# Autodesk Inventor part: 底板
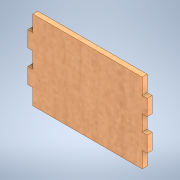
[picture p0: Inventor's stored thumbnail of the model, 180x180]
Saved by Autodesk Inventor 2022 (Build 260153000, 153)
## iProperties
Created: 2024-11
Part Number: 底板
Material: MDF 中密度繊維ボード
Document SubType Name: Modeling
Designer: shimizu
Density: 0.8 g/cm^3
Appearance: サクラ材 - ナチュラル 抑えた光沢
Author: shimizu
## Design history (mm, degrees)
sketch "スケッチ1"
  geometry: L1 (-25.119, 10.226)-(29.881, 10.226); L2 (29.881, -29.774)-(-25.119, -29.774); L3 (-25.119, 2.226)-(-27.619, 2.226); L4 (-27.619, 2.226)-(-27.619, -5.774); L5 (-27.619, -5.774)-(-25.119, -5.774); L6 (-25.119, -13.774)-(-27.619, -13.774); L7 (-27.619, -13.774)-(-27.619, -21.774); L8 (-27.619, -21.774)-(-25.119, -21.774); L9 (29.881, 2.226)-(32.381, 2.226); L10 (32.381, 2.226)-(32.381, -5.774); L11 (32.381, -5.774)-(29.881, -5.774); L12 (29.881, -13.774)-(32.381, -13.774); L13 (32.381, -13.774)-(32.381, -21.774); L14 (32.381, -21.774)-(29.881, -21.774); L15 (-25.119, 2.226)-(-25.119, 10.226); L16 (-25.119, -29.774)-(-25.119, -21.774); L17 (-25.119, -13.774)-(-25.119, -5.774); L18 (29.881, 10.226)-(29.881, 2.226); L19 (29.881, -5.774)-(29.881, -13.774); L20 (29.881, -21.774)-(29.881, -29.774); 1 further point
  constraints: 40 end point, 14 parallel, 7 perpendicular, 5 horizontal
  dimensions: "d16" = 60 distance between parallel lines of L13 L7
extrude "押し出し1" new body sketch "スケッチ1" distance "d2" = 2.5; taper "d3" = 0 deg
node "ソリッド1"
